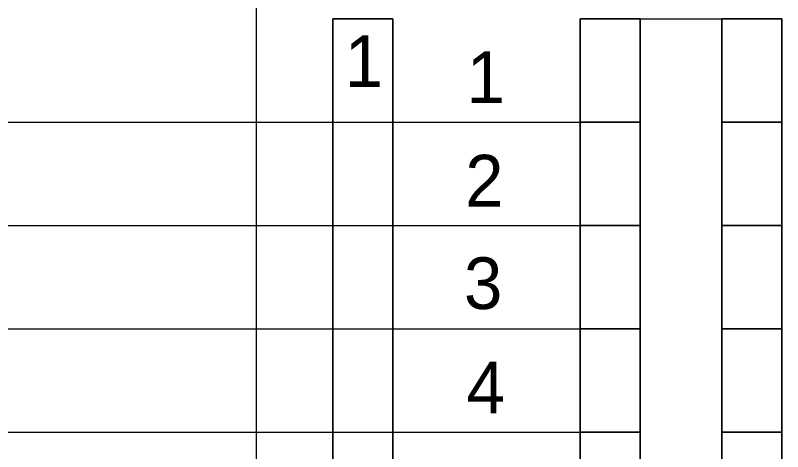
# Model space of a CAD drawing. Extents: x 1901 to 2519, y -3585 to -3154.
# Drawn here: x 2006.66 to 2032.79, y -3217.75 to -3202.89 of the extents above; entities that cross this region are included whole.
import ezdxf

# ---------------------------------------------------------------- set-up
doc = ezdxf.new("R2010")
doc.units = 0
doc.layers.add('rozvláknění', color=7, linetype='Continuous')

msp = doc.modelspace()

# ---------------------------------------------------------------- linework, layer by layer
at = {"layer": 'rozvláknění'}
for p, q in [((1933.193, -3206.524), (2025.898, -3206.527)), ((1933.193, -3210.043), (2025.898, -3210.045)), ((1933.193, -3213.561), (2025.898, -3213.563)), ((1933.193, -3217.079), (2025.898, -3217.081))]:
    msp.add_line(p, q, dxfattribs=at)
for points in [[(2014.869, -3178.545), (2059.522, -3178.544), (2059.522, -3570.656), (2014.869, -3570.656)], [(2019.518, -3245.227), (2017.476, -3245.227), (2017.476, -3203.008), (2019.518, -3203.008)], [(2025.898, -3203.008), (2027.939, -3203.008), (2027.939, -3206.527), (2025.898, -3206.527)], [(2027.939, -3203.008), (2030.726, -3203.008), (2030.726, -3245.223), (2027.939, -3245.223)], [(2030.726, -3203.008), (2032.767, -3203.008), (2032.767, -3206.527), (2030.726, -3206.527)], [(2030.726, -3203.008), (2032.767, -3203.008), (2032.767, -3206.527), (2030.726, -3206.527)], [(2025.898, -3206.527), (2027.939, -3206.527), (2027.939, -3210.045), (2025.898, -3210.045)], [(2030.726, -3206.527), (2032.767, -3206.527), (2032.767, -3210.045), (2030.726, -3210.045)], [(2030.726, -3206.527), (2032.767, -3206.527), (2032.767, -3210.045), (2030.726, -3210.045)], [(2025.898, -3210.045), (2027.939, -3210.045), (2027.939, -3213.563), (2025.898, -3213.563)], [(2030.726, -3210.045), (2032.767, -3210.045), (2032.767, -3213.563), (2030.726, -3213.563)], [(2030.726, -3210.045), (2032.767, -3210.045), (2032.767, -3213.563), (2030.726, -3213.563)], [(2025.898, -3213.563), (2027.939, -3213.563), (2027.939, -3217.081), (2025.898, -3217.081)], [(2030.726, -3213.563), (2032.767, -3213.563), (2032.767, -3217.081), (2030.726, -3217.081)], [(2030.726, -3213.563), (2032.767, -3213.563), (2032.767, -3217.081), (2030.726, -3217.081)], [(2025.898, -3217.081), (2027.939, -3217.081), (2027.939, -3220.599), (2025.898, -3220.599)], [(2030.726, -3217.081), (2032.767, -3217.081), (2032.767, -3220.599), (2030.726, -3220.599)], [(2030.726, -3217.081), (2032.767, -3217.081), (2032.767, -3220.599), (2030.726, -3220.599)]]:
    msp.add_lwpolyline(points, close=True, dxfattribs=at)
for points in [[(2019.518, -3203.008), (2017.476, -3203.008), (2017.476, -3245.227), (2019.518, -3245.227), (2019.518, -3203.008)], [(2019.518, -3203.008), (2017.476, -3203.008), (2017.476, -3245.227), (2019.518, -3245.227), (2019.518, -3203.008)], [(2019.518, -3203.008), (2017.476, -3203.008), (2017.476, -3245.227), (2019.518, -3245.227), (2019.518, -3203.008)], [(2019.518, -3203.008), (2017.476, -3203.008), (2017.476, -3245.227), (2019.518, -3245.227), (2019.518, -3203.008)], [(2019.518, -3203.008), (2017.476, -3203.008), (2017.476, -3245.227), (2019.518, -3245.227), (2019.518, -3203.008)], [(2019.518, -3203.008), (2017.476, -3203.008), (2017.476, -3245.227), (2019.518, -3245.227), (2019.518, -3203.008)], [(2025.898, -3206.527), (2027.939, -3206.527), (2027.939, -3203.008), (2025.898, -3203.008), (2025.898, -3206.527)], [(2025.898, -3206.527), (2027.939, -3206.527), (2027.939, -3203.008), (2025.898, -3203.008), (2025.898, -3206.527)], [(2025.898, -3206.527), (2027.939, -3206.527), (2027.939, -3203.008), (2025.898, -3203.008), (2025.898, -3206.527)], [(2025.898, -3206.527), (2027.939, -3206.527), (2027.939, -3203.008), (2025.898, -3203.008), (2025.898, -3206.527)], [(2025.898, -3206.527), (2027.939, -3206.527), (2027.939, -3203.008), (2025.898, -3203.008), (2025.898, -3206.527)], [(2025.898, -3206.527), (2027.939, -3206.527), (2027.939, -3203.008), (2025.898, -3203.008), (2025.898, -3206.527)], [(2025.898, -3206.527), (2027.939, -3206.527), (2027.939, -3203.008), (2025.898, -3203.008), (2025.898, -3206.527)], [(2025.898, -3206.527), (2027.939, -3206.527), (2027.939, -3203.008), (2025.898, -3203.008), (2025.898, -3206.527)], [(2025.898, -3206.527), (2027.939, -3206.527), (2027.939, -3203.008), (2025.898, -3203.008), (2025.898, -3206.527)], [(2025.898, -3206.527), (2027.939, -3206.527), (2027.939, -3203.008), (2025.898, -3203.008), (2025.898, -3206.527)], [(2030.726, -3206.527), (2032.767, -3206.527), (2032.767, -3203.008), (2030.726, -3203.008), (2030.726, -3206.527)], [(2030.726, -3206.527), (2032.767, -3206.527), (2032.767, -3203.008), (2030.726, -3203.008), (2030.726, -3206.527)], [(2030.726, -3206.527), (2032.767, -3206.527), (2032.767, -3203.008), (2030.726, -3203.008), (2030.726, -3206.527)], [(2030.726, -3206.527), (2032.767, -3206.527), (2032.767, -3203.008), (2030.726, -3203.008), (2030.726, -3206.527)], [(2030.726, -3206.527), (2032.767, -3206.527), (2032.767, -3203.008), (2030.726, -3203.008), (2030.726, -3206.527)], [(2030.726, -3206.527), (2032.767, -3206.527), (2032.767, -3203.008), (2030.726, -3203.008), (2030.726, -3206.527)], [(2030.726, -3206.527), (2032.767, -3206.527), (2032.767, -3203.008), (2030.726, -3203.008), (2030.726, -3206.527)], [(2030.726, -3206.527), (2032.767, -3206.527), (2032.767, -3203.008), (2030.726, -3203.008), (2030.726, -3206.527)], [(2030.726, -3206.527), (2032.767, -3206.527), (2032.767, -3203.008), (2030.726, -3203.008), (2030.726, -3206.527)], [(2030.726, -3206.527), (2032.767, -3206.527), (2032.767, -3203.008), (2030.726, -3203.008), (2030.726, -3206.527)], [(2025.898, -3210.045), (2027.939, -3210.045), (2027.939, -3206.527), (2025.898, -3206.527), (2025.898, -3210.045)], [(2025.898, -3210.045), (2027.939, -3210.045), (2027.939, -3206.527), (2025.898, -3206.527), (2025.898, -3210.045)], [(2025.898, -3210.045), (2027.939, -3210.045), (2027.939, -3206.527), (2025.898, -3206.527), (2025.898, -3210.045)], [(2025.898, -3210.045), (2027.939, -3210.045), (2027.939, -3206.527), (2025.898, -3206.527), (2025.898, -3210.045)], [(2025.898, -3210.045), (2027.939, -3210.045), (2027.939, -3206.527), (2025.898, -3206.527), (2025.898, -3210.045)], [(2025.898, -3210.045), (2027.939, -3210.045), (2027.939, -3206.527), (2025.898, -3206.527), (2025.898, -3210.045)], [(2025.898, -3210.045), (2027.939, -3210.045), (2027.939, -3206.527), (2025.898, -3206.527), (2025.898, -3210.045)], [(2025.898, -3210.045), (2027.939, -3210.045), (2027.939, -3206.527), (2025.898, -3206.527), (2025.898, -3210.045)], [(2025.898, -3210.045), (2027.939, -3210.045), (2027.939, -3206.527), (2025.898, -3206.527), (2025.898, -3210.045)], [(2025.898, -3210.045), (2027.939, -3210.045), (2027.939, -3206.527), (2025.898, -3206.527), (2025.898, -3210.045)], [(2030.726, -3210.045), (2032.767, -3210.045), (2032.767, -3206.527), (2030.726, -3206.527), (2030.726, -3210.045)], [(2030.726, -3210.045), (2032.767, -3210.045), (2032.767, -3206.527), (2030.726, -3206.527), (2030.726, -3210.045)], [(2030.726, -3210.045), (2032.767, -3210.045), (2032.767, -3206.527), (2030.726, -3206.527), (2030.726, -3210.045)], [(2030.726, -3210.045), (2032.767, -3210.045), (2032.767, -3206.527), (2030.726, -3206.527), (2030.726, -3210.045)], [(2030.726, -3210.045), (2032.767, -3210.045), (2032.767, -3206.527), (2030.726, -3206.527), (2030.726, -3210.045)], [(2030.726, -3210.045), (2032.767, -3210.045), (2032.767, -3206.527), (2030.726, -3206.527), (2030.726, -3210.045)], [(2030.726, -3210.045), (2032.767, -3210.045), (2032.767, -3206.527), (2030.726, -3206.527), (2030.726, -3210.045)], [(2030.726, -3210.045), (2032.767, -3210.045), (2032.767, -3206.527), (2030.726, -3206.527), (2030.726, -3210.045)], [(2030.726, -3210.045), (2032.767, -3210.045), (2032.767, -3206.527), (2030.726, -3206.527), (2030.726, -3210.045)], [(2030.726, -3210.045), (2032.767, -3210.045), (2032.767, -3206.527), (2030.726, -3206.527), (2030.726, -3210.045)], [(2025.898, -3213.563), (2027.939, -3213.563), (2027.939, -3210.045), (2025.898, -3210.045), (2025.898, -3213.563)], [(2025.898, -3213.563), (2027.939, -3213.563), (2027.939, -3210.045), (2025.898, -3210.045), (2025.898, -3213.563)], [(2025.898, -3213.563), (2027.939, -3213.563), (2027.939, -3210.045), (2025.898, -3210.045), (2025.898, -3213.563)], [(2025.898, -3213.563), (2027.939, -3213.563), (2027.939, -3210.045), (2025.898, -3210.045), (2025.898, -3213.563)], [(2025.898, -3213.563), (2027.939, -3213.563), (2027.939, -3210.045), (2025.898, -3210.045), (2025.898, -3213.563)], [(2025.898, -3213.563), (2027.939, -3213.563), (2027.939, -3210.045), (2025.898, -3210.045), (2025.898, -3213.563)], [(2025.898, -3213.563), (2027.939, -3213.563), (2027.939, -3210.045), (2025.898, -3210.045), (2025.898, -3213.563)], [(2025.898, -3213.563), (2027.939, -3213.563), (2027.939, -3210.045), (2025.898, -3210.045), (2025.898, -3213.563)], [(2025.898, -3213.563), (2027.939, -3213.563), (2027.939, -3210.045), (2025.898, -3210.045), (2025.898, -3213.563)], [(2025.898, -3213.563), (2027.939, -3213.563), (2027.939, -3210.045), (2025.898, -3210.045), (2025.898, -3213.563)], [(2030.726, -3213.563), (2032.767, -3213.563), (2032.767, -3210.045), (2030.726, -3210.045), (2030.726, -3213.563)], [(2030.726, -3213.563), (2032.767, -3213.563), (2032.767, -3210.045), (2030.726, -3210.045), (2030.726, -3213.563)], [(2030.726, -3213.563), (2032.767, -3213.563), (2032.767, -3210.045), (2030.726, -3210.045), (2030.726, -3213.563)], [(2030.726, -3213.563), (2032.767, -3213.563), (2032.767, -3210.045), (2030.726, -3210.045), (2030.726, -3213.563)], [(2030.726, -3213.563), (2032.767, -3213.563), (2032.767, -3210.045), (2030.726, -3210.045), (2030.726, -3213.563)], [(2030.726, -3213.563), (2032.767, -3213.563), (2032.767, -3210.045), (2030.726, -3210.045), (2030.726, -3213.563)], [(2030.726, -3213.563), (2032.767, -3213.563), (2032.767, -3210.045), (2030.726, -3210.045), (2030.726, -3213.563)], [(2030.726, -3213.563), (2032.767, -3213.563), (2032.767, -3210.045), (2030.726, -3210.045), (2030.726, -3213.563)], [(2030.726, -3213.563), (2032.767, -3213.563), (2032.767, -3210.045), (2030.726, -3210.045), (2030.726, -3213.563)], [(2030.726, -3213.563), (2032.767, -3213.563), (2032.767, -3210.045), (2030.726, -3210.045), (2030.726, -3213.563)], [(2025.898, -3217.081), (2027.939, -3217.081), (2027.939, -3213.563), (2025.898, -3213.563), (2025.898, -3217.081)], [(2025.898, -3217.081), (2027.939, -3217.081), (2027.939, -3213.563), (2025.898, -3213.563), (2025.898, -3217.081)], [(2025.898, -3217.081), (2027.939, -3217.081), (2027.939, -3213.563), (2025.898, -3213.563), (2025.898, -3217.081)], [(2025.898, -3217.081), (2027.939, -3217.081), (2027.939, -3213.563), (2025.898, -3213.563), (2025.898, -3217.081)], [(2025.898, -3217.081), (2027.939, -3217.081), (2027.939, -3213.563), (2025.898, -3213.563), (2025.898, -3217.081)], [(2025.898, -3217.081), (2027.939, -3217.081), (2027.939, -3213.563), (2025.898, -3213.563), (2025.898, -3217.081)], [(2025.898, -3217.081), (2027.939, -3217.081), (2027.939, -3213.563), (2025.898, -3213.563), (2025.898, -3217.081)], [(2025.898, -3217.081), (2027.939, -3217.081), (2027.939, -3213.563), (2025.898, -3213.563), (2025.898, -3217.081)], [(2025.898, -3217.081), (2027.939, -3217.081), (2027.939, -3213.563), (2025.898, -3213.563), (2025.898, -3217.081)], [(2025.898, -3217.081), (2027.939, -3217.081), (2027.939, -3213.563), (2025.898, -3213.563), (2025.898, -3217.081)], [(2030.726, -3217.081), (2032.767, -3217.081), (2032.767, -3213.563), (2030.726, -3213.563), (2030.726, -3217.081)], [(2030.726, -3217.081), (2032.767, -3217.081), (2032.767, -3213.563), (2030.726, -3213.563), (2030.726, -3217.081)], [(2030.726, -3217.081), (2032.767, -3217.081), (2032.767, -3213.563), (2030.726, -3213.563), (2030.726, -3217.081)], [(2030.726, -3217.081), (2032.767, -3217.081), (2032.767, -3213.563), (2030.726, -3213.563), (2030.726, -3217.081)], [(2030.726, -3217.081), (2032.767, -3217.081), (2032.767, -3213.563), (2030.726, -3213.563), (2030.726, -3217.081)], [(2030.726, -3217.081), (2032.767, -3217.081), (2032.767, -3213.563), (2030.726, -3213.563), (2030.726, -3217.081)], [(2030.726, -3217.081), (2032.767, -3217.081), (2032.767, -3213.563), (2030.726, -3213.563), (2030.726, -3217.081)], [(2030.726, -3217.081), (2032.767, -3217.081), (2032.767, -3213.563), (2030.726, -3213.563), (2030.726, -3217.081)], [(2030.726, -3217.081), (2032.767, -3217.081), (2032.767, -3213.563), (2030.726, -3213.563), (2030.726, -3217.081)], [(2030.726, -3217.081), (2032.767, -3217.081), (2032.767, -3213.563), (2030.726, -3213.563), (2030.726, -3217.081)], [(2025.898, -3220.599), (2027.939, -3220.599), (2027.939, -3217.081), (2025.898, -3217.081), (2025.898, -3220.599)], [(2025.898, -3220.599), (2027.939, -3220.599), (2027.939, -3217.081), (2025.898, -3217.081), (2025.898, -3220.599)], [(2025.898, -3220.599), (2027.939, -3220.599), (2027.939, -3217.081), (2025.898, -3217.081), (2025.898, -3220.599)], [(2025.898, -3220.599), (2027.939, -3220.599), (2027.939, -3217.081), (2025.898, -3217.081), (2025.898, -3220.599)], [(2025.898, -3220.599), (2027.939, -3220.599), (2027.939, -3217.081), (2025.898, -3217.081), (2025.898, -3220.599)], [(2025.898, -3220.599), (2027.939, -3220.599), (2027.939, -3217.081), (2025.898, -3217.081), (2025.898, -3220.599)], [(2025.898, -3220.599), (2027.939, -3220.599), (2027.939, -3217.081), (2025.898, -3217.081), (2025.898, -3220.599)], [(2025.898, -3220.599), (2027.939, -3220.599), (2027.939, -3217.081), (2025.898, -3217.081), (2025.898, -3220.599)], [(2025.898, -3220.599), (2027.939, -3220.599), (2027.939, -3217.081), (2025.898, -3217.081), (2025.898, -3220.599)], [(2025.898, -3220.599), (2027.939, -3220.599), (2027.939, -3217.081), (2025.898, -3217.081), (2025.898, -3220.599)], [(2030.726, -3220.599), (2032.767, -3220.599), (2032.767, -3217.081), (2030.726, -3217.081), (2030.726, -3220.599)], [(2030.726, -3220.599), (2032.767, -3220.599), (2032.767, -3217.081), (2030.726, -3217.081), (2030.726, -3220.599)], [(2030.726, -3220.599), (2032.767, -3220.599), (2032.767, -3217.081), (2030.726, -3217.081), (2030.726, -3220.599)], [(2030.726, -3220.599), (2032.767, -3220.599), (2032.767, -3217.081), (2030.726, -3217.081), (2030.726, -3220.599)], [(2030.726, -3220.599), (2032.767, -3220.599), (2032.767, -3217.081), (2030.726, -3217.081), (2030.726, -3220.599)], [(2030.726, -3220.599), (2032.767, -3220.599), (2032.767, -3217.081), (2030.726, -3217.081), (2030.726, -3220.599)], [(2030.726, -3220.599), (2032.767, -3220.599), (2032.767, -3217.081), (2030.726, -3217.081), (2030.726, -3220.599)], [(2030.726, -3220.599), (2032.767, -3220.599), (2032.767, -3217.081), (2030.726, -3217.081), (2030.726, -3220.599)], [(2030.726, -3220.599), (2032.767, -3220.599), (2032.767, -3217.081), (2030.726, -3217.081), (2030.726, -3220.599)], [(2030.726, -3220.599), (2032.767, -3220.599), (2032.767, -3217.081), (2030.726, -3217.081), (2030.726, -3220.599)]]:
    msp.add_lwpolyline(points, dxfattribs=at)

# ---------------------------------------------------------------- texts
for s, p in [('1', (2017.875, -3205.334)), ('1', (2022.026, -3205.88)), ('2', (2021.979, -3209.4)), ('3', (2021.937, -3212.89)), ('4', (2022.026, -3216.44))]:
    msp.add_text(s, height=1.76, dxfattribs=at).set_placement(p)

doc.saveas('drawing.dxf')
